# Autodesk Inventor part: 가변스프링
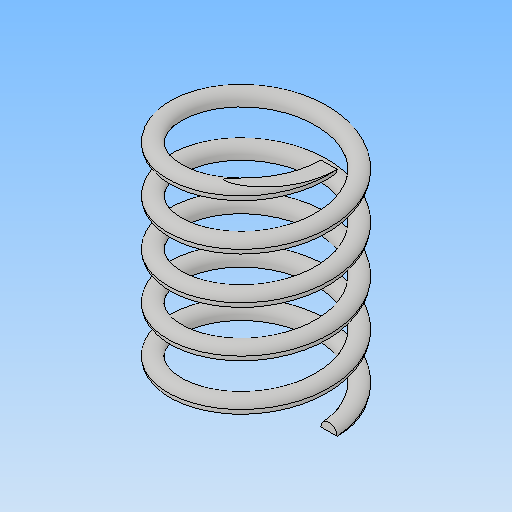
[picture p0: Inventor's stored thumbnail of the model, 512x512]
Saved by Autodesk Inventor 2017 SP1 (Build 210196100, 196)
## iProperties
Part Number: 가변스프링
Material: 일반
Document SubType Name: Modeling
Designer: MRC
Density: 1 g/cm^3
Appearance: 기본값
Author: MRC
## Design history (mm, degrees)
sketch "스케치1"
  geometry: L1 (0, 0)-(9, 0); L2 (9, 0)-(9, -28.5); L3 (9, -28.5)-(0, -28.5); L4 (0, -28.5)-(0, 0); C1 r 1 at (9, 0)
  constraints: 8 end point, 2 parallel, 1 centre point, 1 coincident, 1 horizontal, 1 perpendicular
  dimensions: "d0" = 18 diameter of L2 L4; "d1" = 2 diameter of C1; "d2" = 28.5 distance between parallel lines of L1 L3 (derived)
feature "코일1" sketch "스케치1" pitch "d3" = 10; turns "d5" = 5; dims "d4" = 28.5 (= d2), "d6" = 0, angle "d7" = 90 deg, angle "d8" = 90 deg, "d9" = 0, "d10" = 0
sketch "스케치2"
  geometry: L1 (-20.357, -28.5)-(20.357, -28.5); L2 (20.357, -28.5)-(20.357, 0); L3 (20.357, 0)-(-20.357, 0); L4 (-20.357, 0)-(-20.357, -28.5); L5 (9, -28.5)-(0, -28.5) reference; 2 further points
  constraints: 8 end point, 2 midpoint, 2 parallel, 1 coincident, 1 horizontal, 1 perpendicular
  dimensions: "d11" = 40.71422 distance of L1.start L1.end
extrude "돌출1" sketch "스케치2" stored distance "d12" = 0; taper "d13" = 0 deg
node "솔리드1"
